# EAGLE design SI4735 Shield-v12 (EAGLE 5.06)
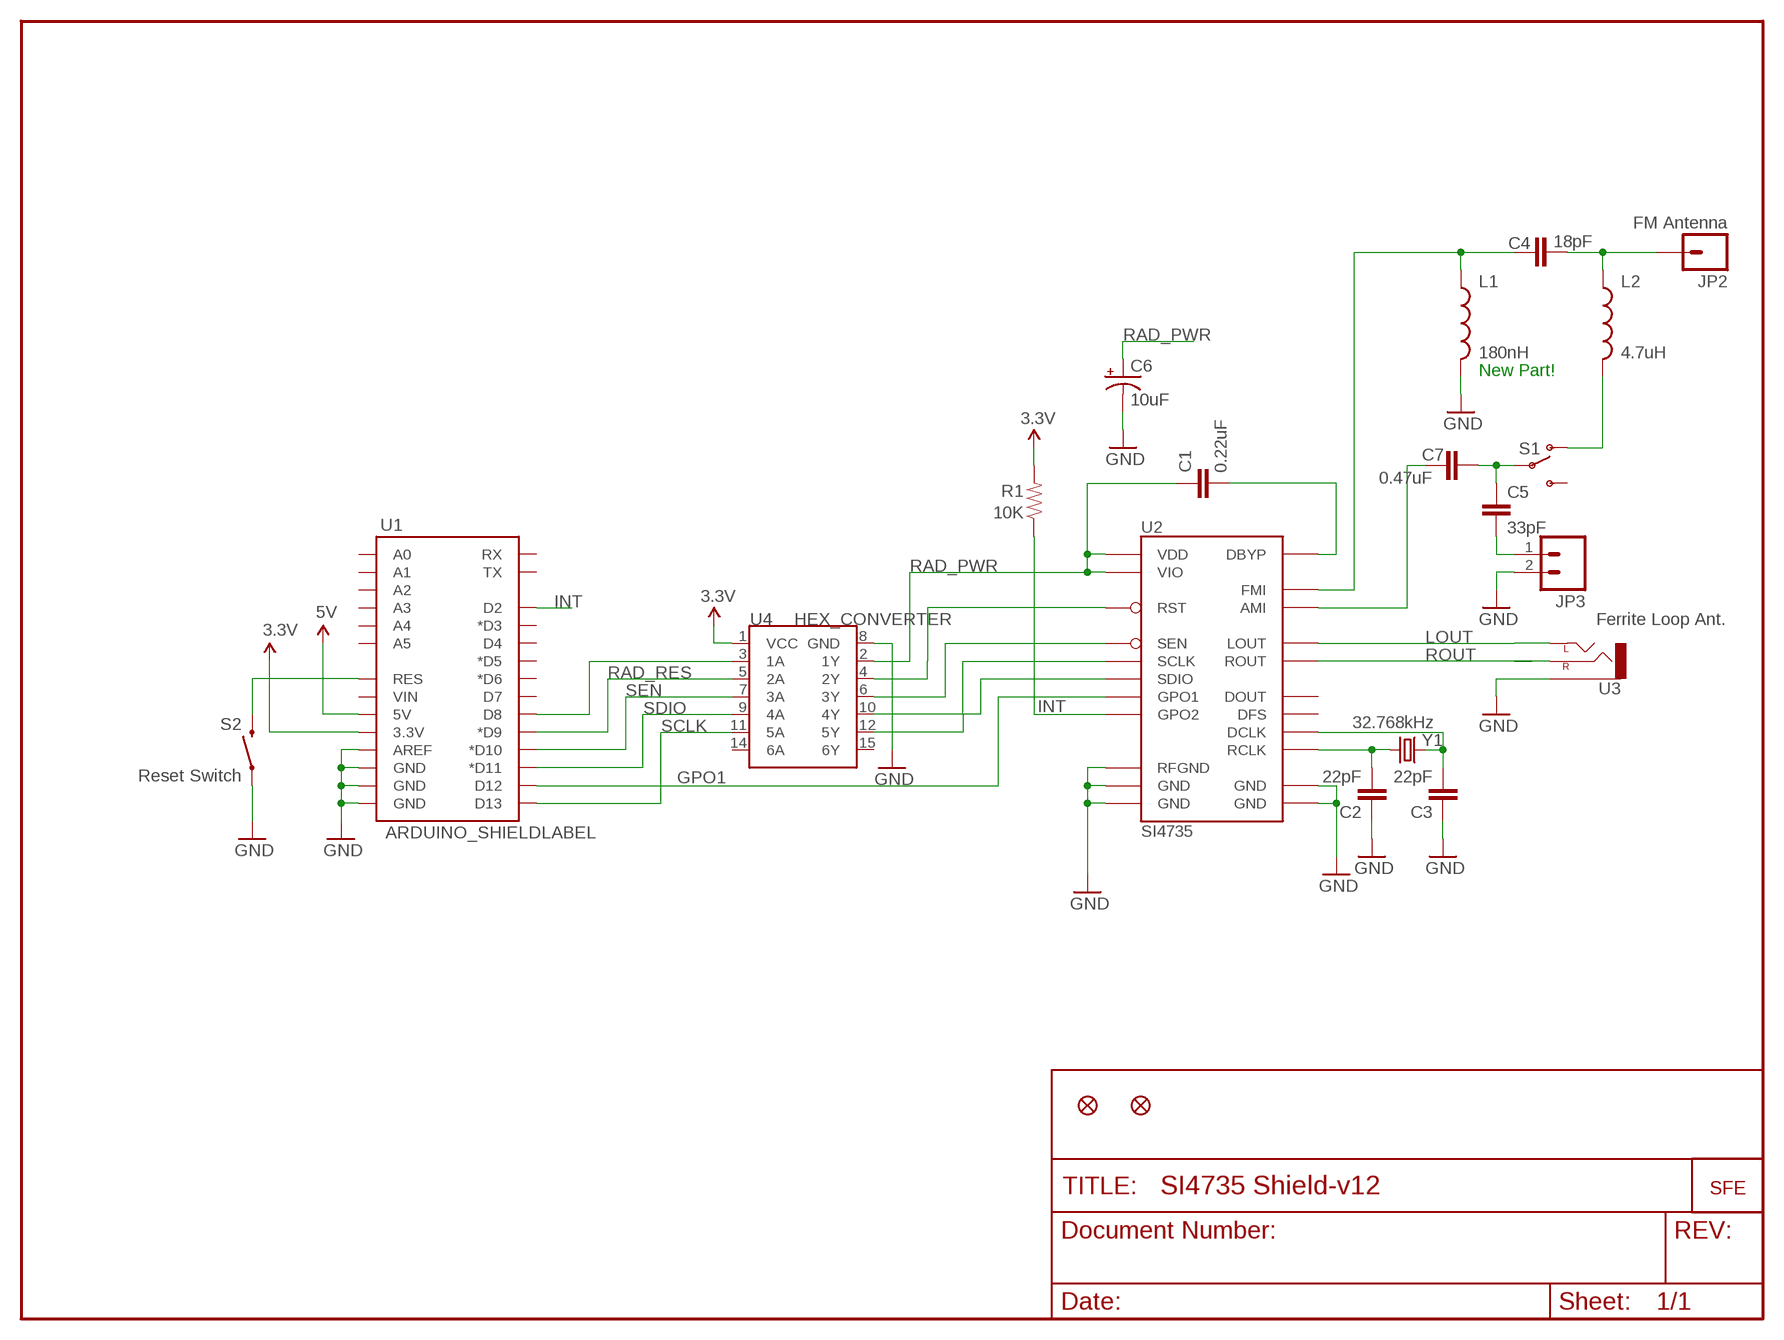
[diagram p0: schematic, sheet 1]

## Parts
C1  0.22uF  CAP0402-CAP  [0402-CAP]
C2  22pF  CAP0402-CAP  [0402-CAP]
C3  22pF  CAP0402-CAP  [0402-CAP]
C4  18pF  CAP0402-CAP  [0402-CAP]
C5  33pF  CAP0402-CAP  [0402-CAP]
C6  10uF  CAP_POL3528  [EIA3528]
C7  0.47uF  CAP0402-CAP  [0402-CAP]
JP1  LOGO-SFENEW  [SFE-NEW-WEBLOGO]
JP2  FM Antenna  M01PTH  [1X01]
JP3  Ferrite Loop Ant.  M02PTH  [1X02]
JP4  FIDUCIAL1X2  [FIDUCIAL-1X2]
JP5  FIDUCIAL1X2  [FIDUCIAL-1X2]
L1  180nH  INDUCTOR0402  [C0402]
L2  4.7uH  INDUCTOR0402  [C0402]
R1  10K  RESISTOR0402-RES  [0402-RES]
S1  SWITCH-SPSTSMD  [AYZ0202]
S2  Reset Switch  SWITCH-MOMENTARY-2SMD  [TACTILE_SWITCH_SMD]
U1  ARDUINO_SHIELDLABEL  [DUEMILANOVE_SHIELD]
U2  SI4735  [SSOP24_NARROW]
U3  AUDIO-JACKSMD2  [AUDIO-JACK-3.5MM-SMD]
U4  HEX_CONVERTER  [SO016]
Y1  32.768kHz  CRYSTAL32-SMD  [CRYSTAL-32KHZ-SMD]

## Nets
3.3V: R1.2 U1.3.3V U4.1(VCC)
5V: U1.5V
GND: C2.1 C3.1 C6.C(-) JP3.2 L1.2 S2.1 U1.AREF U1.GND@0(GND) U1.GND@1(GND) U1.GND@2(GND) U2.9(RFGND) U2.10(GND) U2.11(GND) U2.13(GND) U2.14(GND) U3.SLEEVE U4.8(GND)
GPO1: U1.D12 U2.5(GPO1)
INT: R1.1 U1.D2 U2.4(GPO2)
LOUT: U2.24(LOUT) U3.TIP(LEFT)
N$1: C2.2 U2.19(RCLK) Y1.X1
N$2: C3.2 U2.3(DCLK) Y1.X2
N$3: S2.3 U1.RES
N$4: C1.2 U2.22(DBYP)
N$5: U2.15(RST) U4.4(2Y)
N$12: U2.16(SEN) U4.6(3Y)
N$15: U2.17(SCLK) U4.12(5Y)
N$16: U2.18(SDIO) U4.10(4Y)
N$17: C4.1 L1.1 U2.8(FMI)
N$20: U1.D8 U4.3(1A)
N$21: C4.2 JP2.1 L2.1
N$22: L2.2 S1.1(O)
N$23: C5.1 C7.1 S1.2(P)
N$34: C7.2 U2.12(AMI)
N$35: C5.2 JP3.1
RAD_PWR: C1.1 C6.A(+) U2.20(VIO) U2.21(VDD) U4.2(1Y)
RAD_RES: U1.D9(*D9) U4.5(2A)
ROUT: U2.23(ROUT) U3.RING(RIGHT)
SCLK: U1.D13 U4.11(5A)
SDIO: U1.D11(*D11) U4.9(4A)
SEN: U1.D10(*D10) U4.7(3A)
Unconnected: S1.3(S) U1.A0 U1.A1 U1.A2 U1.A3 U1.A4 U1.A5 U1.D3(*D3) U1.D4 U1.D5(*D5) U1.D6(*D6) U1.D7 U1.RX U1.TX U1.VIN U2.1(DOUT) U2.2(DFS) U4.14(6A) U4.15(6Y)

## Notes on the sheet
- New Part!

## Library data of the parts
C1-C5 C7 = SparkFun:CAP: Capacitor
C6 = SparkFun:CAP_POL: Capacitor Polarized
JP1 = SparkFun:LOGO-SFE: Spark Fun Electronics PCB Logo
JP2 = SparkFun:M01: Header 1
JP3 = SparkFun:M02: Header 2
JP4 JP5 = SparkFun:FIDUCIAL: Fiducial Alignment Points
L1 L2 = SparkFun:INDUCTOR: Inductors
R1 = SparkFun:RESISTOR: Resistor
S1 = SparkFun:SWITCH-SPST: SPST Switch Simple slide switch. Spark Fun Electronics SKU : COM-00102
S2 = SparkFun:SWITCH-MOMENTARY-2
U1 = SparkFun:ARDUINO_SHIELD
U2 = SparkFun:SI4735: Radio chip that covers FM broadcast with RDS, plus a bunch of shortwave and logwave frequencies
U3 = SparkFun:AUDIO-JACK: 3.5mm Audio Jack Simple 3.5mm common PCB mount audio jack. SKU: PRT-08032
U4 = SparkFun:HEX_CONVERTER
Y1 = SparkFun:CRYSTAL: Crystals

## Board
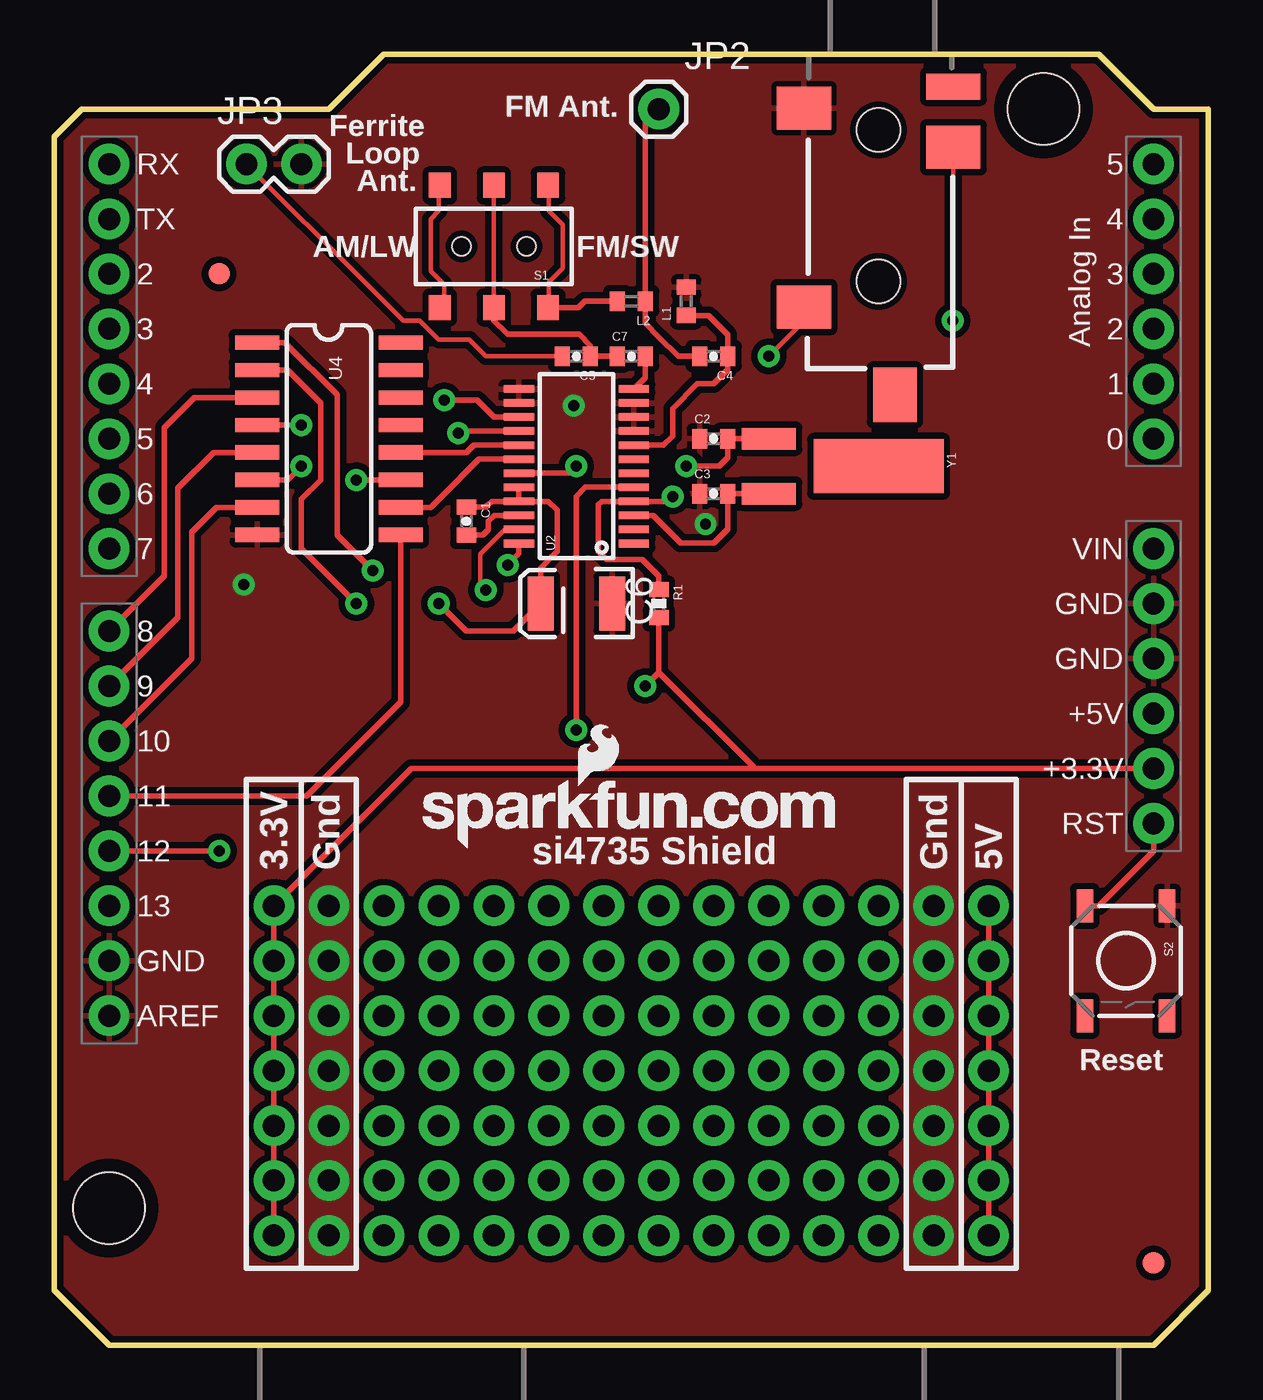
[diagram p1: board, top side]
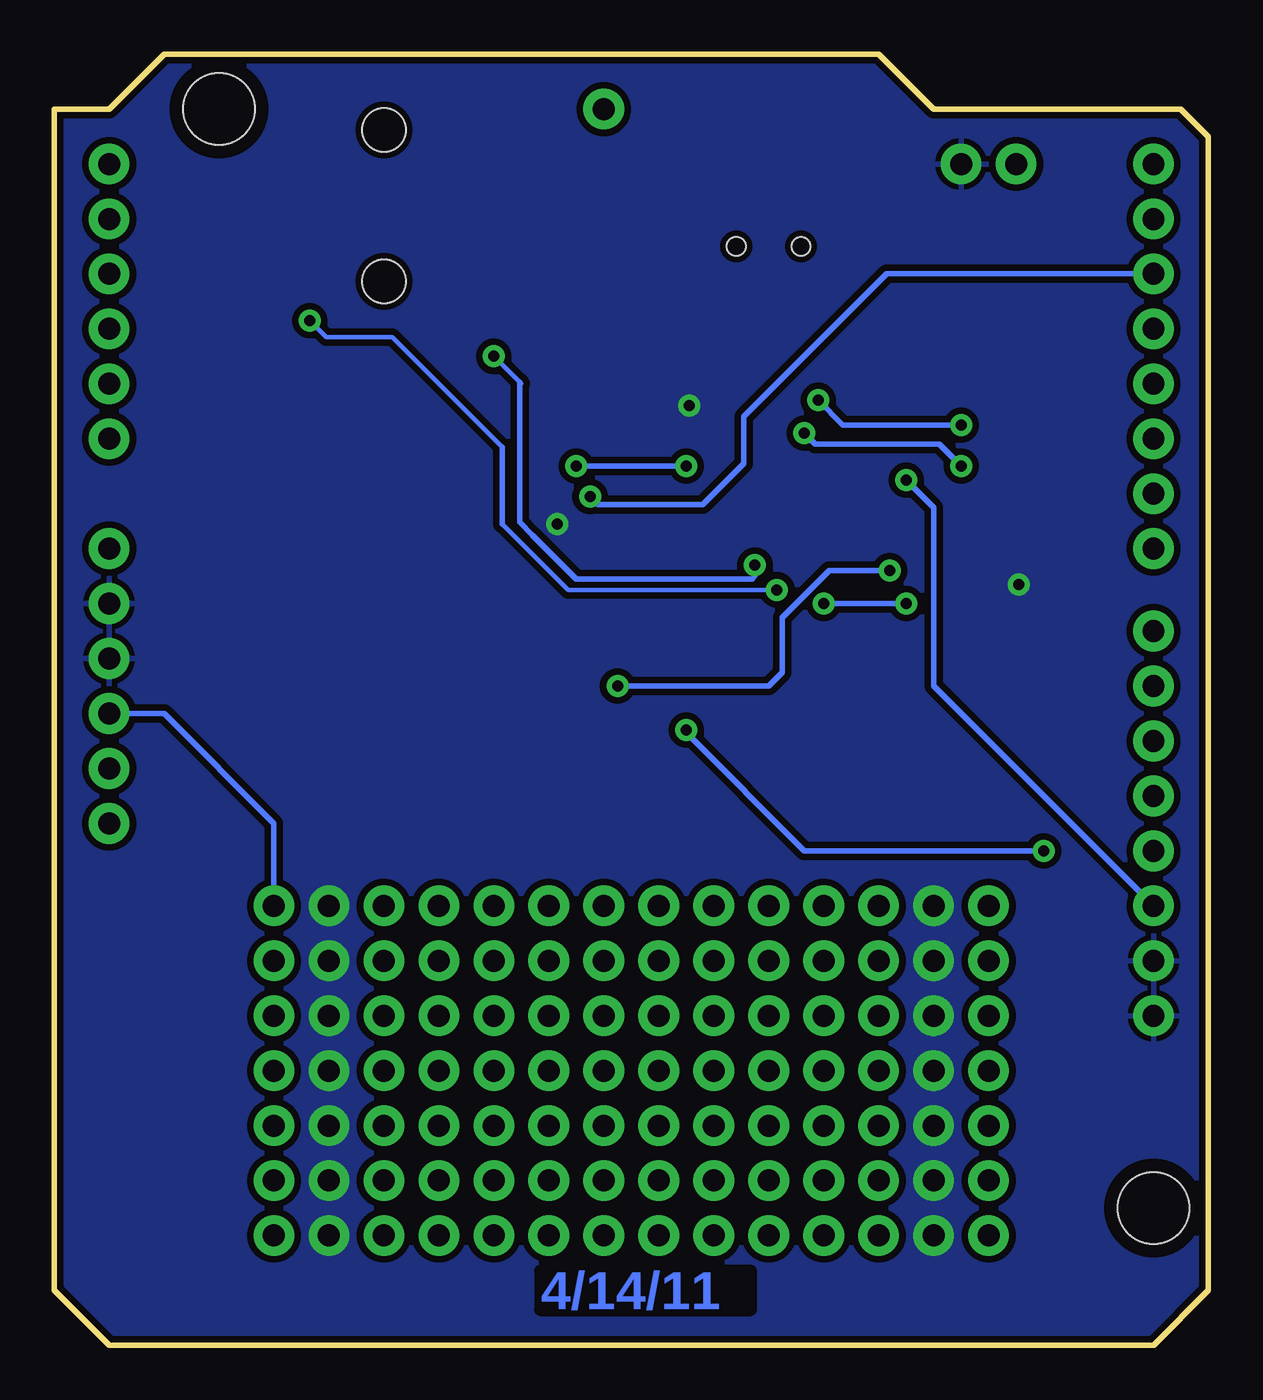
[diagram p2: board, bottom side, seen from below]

Size 53.34 x 59.69 mm. Coordinates in mm from the lower left corner, seen from the top.
Outline: 0,2.54 0,55.88 1.27,57.15 12.7,57.15 15.24,59.69 48.26,59.69 50.8,57.15 53.34,57.15 53.34,2.54 50.8,0 2.54,0 0,2.54
Copper layers (1*16): Top 0.035mm / dielectric 1.5mm / Bottom 0.035mm
Design rules "SparkFun": minimum track width 8mil, minimum drill 20mil, track to track 8mil, track to pad 8mil, pad to pad 8mil, via to via 8mil, smd to smd 8mil, copper to edge 8mil, drill to drill 8mil, minimum pad ring 12mil, minimum via ring 10mil, stop-mask expansion 4mil, vias tented up to drill 20mil, thermal gap 10mil

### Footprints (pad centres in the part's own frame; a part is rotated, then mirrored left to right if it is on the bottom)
0402-CAP = smd 0.7 x 0.9: 1 -0.65,0; 2 0.65,0
EIA3528 = smd 1.2 x 2.5: A 1.65,0; C -1.65,0
1X01 = drill 1.016 pad 1.88 round: 1 0,0
1X02 = drill 1.016 pad 1.88 round: 1 0,0; 2 2.54,0
FIDUCIAL-1X2 = smd 1 x 1: 1 0,0
C0402 = smd 0.7 x 0.9: 1 -0.65,0; 2 0.65,0
0402-RES = smd 0.7 x 0.9: 1 -0.65,0; 2 0.65,0
AYZ0202 = smd 1 x 1.15: 1 -2.5,2.825; 2 0,2.825; 3 2.5,2.825; 4 -2.5,-2.825; 5 0,-2.825; 6 2.5,-2.825 | hole 0.85: 1.5,0; -1.5,0
TACTILE_SWITCH_SMD = smd 1.524 x 0.762: 1 -2.54,1.905; 2 2.54,1.905; 3 -2.54,-1.905; 4 2.54,-1.905
DUEMILANOVE_SHIELD = drill 1.016 pad 1.88 round: 3.3V 50.8,26.67; 5V 50.8,29.21; A0 50.8,41.91; A1 50.8,44.45; A2 50.8,46.99; A3 50.8,49.53; A4 50.8,52.07; A5 50.8,54.61; AREF 2.54,15.24; D2 2.54,49.53; D3 2.54,46.99; D4 2.54,44.45; D5 2.54,41.91; D6 2.54,39.37; D7 2.54,36.83; D8 2.54,33.02; D9 2.54,30.48; D10 2.54,27.94; D11 2.54,25.4; D12 2.54,22.86; D13 2.54,20.32; GND@0 50.8,31.75; GND@1 50.8,34.29; GND@2 2.54,17.78; RES 50.8,24.13; RX 2.54,54.61; TX 2.54,52.07; VIN 50.8,36.83 | hole 3.302: 45.72,57.15; 2.54,6.35
SSOP24_NARROW = smd 0.348 x 1.397: 1 -3.575,-2.65; 2 -2.925,-2.65; 3 -2.275,-2.65; 4 -1.625,-2.65; 5 -0.975,-2.65; 6 -0.325,-2.65; 7 0.325,-2.65; 8 0.975,-2.65; 9 1.625,-2.65; 10 2.275,-2.65; 11 2.925,-2.65; 12 3.575,-2.65; 13 3.575,2.65; 14 2.925,2.65; 15 2.275,2.65; 16 1.625,2.65; 17 0.975,2.65; 18 0.325,2.65; 19 -0.325,2.65; 20 -0.975,2.65; 21 -1.625,2.65; 22 -2.275,2.65; 23 -2.925,2.65; 24 -3.575,2.65
AUDIO-JACK-3.5MM-SMD = smd 2 x 2.5: RING 4.3,3.45; SLEEVE 2.5,-3.45; TIP 11.7,-3.45 | smd 1.2 x 2.5: RSH 1.5,3.45 | smd 2.5 x 2: TSH 15.75,0.75 | hole 2: 3.5,0; 10.5,0
SO016 = smd 0.66 x 2.032: 1 -4.445,-3.315; 2 -3.175,-3.315; 3 -1.905,-3.315; 4 -0.635,-3.315; 5 0.635,-3.315; 6 1.905,-3.315; 7 3.175,-3.315; 8 4.445,-3.315; 9 4.445,3.315; 10 3.175,3.315; 11 1.905,3.315; 12 0.635,3.315; 13 -0.635,3.315; 14 -1.905,3.315; 15 -3.175,3.315; 16 -4.445,3.315
CRYSTAL-32KHZ-SMD = smd 2.5 x 6: SHEILD 0,5.08 | smd 1 x 2.5: X1 -1.27,0; X2 1.27,0

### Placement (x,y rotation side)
C1  19.05,38.1 270 top
C2  30.48,41.91 0 top
C3  30.48,39.37 0 top
C4  30.48,45.72 180 top
C5  24.13,45.72 180 top
C6  24.13,34.29 180 top
C7  26.67,45.72 0 top
JP1  17.02,22.99 0 top
JP2  27.94,57.15 0 top
JP3  8.89,54.61 0 top
JP4  50.8,3.81 0 top
JP5  7.62,49.53 0 top
L1  29.21,48.26 90 top
L2  26.67,48.26 180 top
R1  27.94,34.29 270 top
S1  20.32,50.8 180 top
S2  49.53,17.78 270 top
U1  0,0 0 top
U2  24.13,40.64 90 top
U3  38.1,59.69 270 top
U4  12.7,41.91 270 top
Y1  33.02,40.64 270 top

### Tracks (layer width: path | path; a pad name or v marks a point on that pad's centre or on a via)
3.3V  (via drill 0.51, 1.02 pad 1.88)
  Top 0.254: U4.1 10.67,46.35 13.08,43.94 13.08,39.88 13.08,37.47 v14.73,35.81 | 27.94,31.11 v27.3,30.48 | 27.94,31.11 R1.2 | U1.3.3V 32.38,26.67 32.32,26.73 | 32.32,26.73 27.94,31.11 | v10.16,5.08 v10.16,7.62 v10.16,10.16 v10.16,12.7 v10.16,15.24 v10.16,17.78 v10.16,20.32 16.51,26.67 32.26,26.67 32.32,26.73
  Bottom 0.254: v27.3,30.48 20.32,30.48 19.68,31.11 19.68,33.66 17.53,35.81 v14.73,35.81
5V  (via drill 1.02 pad 1.88)
  Top 0.254: v43.18,20.32 v43.18,17.78 v43.18,15.24 v43.18,12.7 v43.18,10.16 v43.18,7.62 v43.18,5.08
  Bottom 0.254: U1.5V 48.26,29.21 43.18,24.13 v43.18,20.32
GND  (via drill 0.51, 1.02 pad 1.88)
  other vias: 24,43.43 8.76,35.18 30.1,37.97 40.64,20.32 40.64,17.78 40.64,15.24 40.64,12.7 40.64,10.16 40.64,7.62 40.64,5.08 12.7,20.32 12.7,17.78 12.7,15.24 12.7,12.7 12.7,10.16 12.7,7.62 12.7,5.08
  pour Bottom (isolate 0.305): 0,0 0,59.69 53.34,59.69 53.34,0
  pour Top (isolate 0.305): 0,0 0,57.15 2.54,59.69 52.07,59.69 53.34,58.42 53.34,2.54 50.8,0
GPO1  (via drill 0.51)
  Top 0.254: U2.5 25.06,39.66 24.55,39.66 24.13,39.24 v24.13,28.45 | U1.D12 v7.62,22.86
  Bottom 0.254: v24.13,28.45 24.13,28.32 18.67,22.86 v7.62,22.86
INT  (via drill 0.51)
  Top 0.254: R1.1 27.94,35.43 27.94,35.56 27.18,36.32 25.53,36.32 25.15,36.7 25.15,38.86 25.3,39.02 U2.4 28.35,39.02 v28.57,39.24
  Bottom 0.254: U1.D2 14.86,49.53 21.46,42.93 21.46,40.77 23.37,38.86 28.19,38.86 v28.57,39.24
LOUT  (via drill 0.51)
  Top 0.203: U3.TIP 34.65,47.35 v33.02,45.72
  Top 0.254: U2.24 21.48,36.59 v20.95,36.07
  Bottom 0.203: 31.83,44.45 31.75,44.45 v33.02,45.72
  Bottom 0.254: v20.95,36.07 20.95,35.56 21.08,35.43 29.21,35.43 31.24,37.47 31.83,38.05 31.83,44.45 31.83,44.53
N$1  (via drill 0.51)
  Top 0.254: Y1.X1 32.89,41.91 C2.2 31.13,41.04 30.99,40.89 30.73,40.64 v29.21,40.64 | U2.19 23.8,40.31 v24.13,40.64
  Bottom 0.254: v24.13,40.64 v29.21,40.64
N$2
  Top 0.254: Y1.X2 C3.2 31.13,37.73 31.11,37.72 30.73,37.34 30.48,37.08 28.96,37.08 27.68,38.37 U2.3
N$3
  Top 0.254: U1.RES 50.8,22.86 48.26,20.32 48.13,20.32 S2.3
N$4
  Top 0.254: C1.2 19.8,37.45 20.07,37.72 20.07,38.1 20.33,38.37 U2.22
N$5  (via drill 0.51)
  Top 0.254: U4.4 v11.43,42.55 | U2.15 20.33,42.91 19.56,43.69 v18.03,43.69
  Bottom 0.254: v11.43,42.55 16.89,42.55 v18.03,43.69
N$6  (via drill 1.02 pad 1.88)
  other vias: 15.24,5.08
N$7  (via drill 1.02 pad 1.88)
  other vias: 17.78,5.08
N$8  (via drill 1.02 pad 1.88)
  other vias: 20.32,5.08
N$9  (via drill 1.02 pad 1.88)
  other vias: 22.86,5.08
N$10  (via drill 1.02 pad 1.88)
  other vias: 25.4,5.08
N$11  (via drill 1.02 pad 1.88)
  other vias: 27.94,5.08
N$12  (via drill 0.51)
  Top 0.254: U4.6 10.79,40.01 v11.43,40.64 | U2.16 18.77,42.27 v18.67,42.16
  Bottom 0.254: v18.67,42.16 18.16,41.66 14.99,41.66 12.45,41.66 v11.43,40.64
N$13  (via drill 1.02 pad 1.88)
  other vias: 30.48,5.08
N$14  (via drill 1.02 pad 1.88)
  other vias: 33.02,5.08
N$15
  Top 0.254: U4.12 19.05,41.27 19.3,41.53 19.39,41.62 U2.17
N$16
  Top 0.254: U4.10 17.4,38.73 17.91,39.24 19.63,40.97 U2.18
N$17
  Top 0.254: L1.1 30.24,47.61 31.11,46.74 31.13,46.72 C4.1 31.13,45.1 31.11,45.09 30.48,44.45 29.72,44.45 28.57,43.31 28.57,42.04 28.15,41.62 U2.8
N$18  (via drill 1.02 pad 1.88)
  other vias: 35.56,5.08
N$19  (via drill 1.02 pad 1.88)
  other vias: 38.1,5.08
N$20
  Top 0.254: U1.D8 5.08,35.56 5.08,42.42 6.48,43.81 U4.3
N$21
  Top 0.254: C4.2 29.72,45.72 28.83,45.72 27.94,46.61 27.3,47.24 27.3,48.26 L2.1 27.32,56.53 JP2.1
N$22
  Top 0.254: S1.1 24.23,47.98 24.51,48.26 24.64,48.26 L2.2
N$23
  Top 0.203: 20.32,47.88 20.32,53.59
  Top 0.254: C7.1 26.04,45.72 C5.1 24.78,46.21 24.26,46.74 24.13,46.74 20.95,46.74 20.32,47.37 20.32,47.88 S1.2
N$24  (via drill 1.02 pad 1.88)
  other vias: 38.1,7.62
N$25  (via drill 1.02 pad 1.88)
  other vias: 35.56,7.62
N$26  (via drill 1.02 pad 1.88)
  other vias: 33.02,7.62
N$27  (via drill 1.02 pad 1.88)
  other vias: 30.48,7.62
N$28  (via drill 1.02 pad 1.88)
  other vias: 27.94,7.62
N$29  (via drill 1.02 pad 1.88)
  other vias: 25.4,7.62
N$30  (via drill 1.02 pad 1.88)
  other vias: 22.86,7.62
N$31  (via drill 1.02 pad 1.88)
  other vias: 20.32,7.62
N$32  (via drill 1.02 pad 1.88)
  other vias: 17.78,7.62
N$33  (via drill 1.02 pad 1.88)
  other vias: 15.24,7.62
N$34
  Top 0.254: C7.2 27.3,45.72 27.3,44.74 U2.12
N$35
  Top 0.203: C5.2 19.94,45.72 19.18,46.48 19.05,46.48 17.78,46.48 16.89,47.37 16.64,47.37 16.13,47.37 14.35,49.15 JP3.1
N$36
  Top 0.203: 18.03,48.01 18.03,49.02 17.4,49.66 17.4,52.07 17.78,52.45 17.78,53.59
N$37
  Top 0.203: 22.86,48.01 22.86,49.15 23.5,49.78 23.5,51.82 22.86,52.45 22.86,53.72
N$38  (via drill 1.02 pad 1.88)
  other vias: 15.24,10.16
N$39  (via drill 1.02 pad 1.88)
  other vias: 17.78,10.16
N$40  (via drill 1.02 pad 1.88)
  other vias: 20.32,10.16
N$41  (via drill 1.02 pad 1.88)
  other vias: 22.86,10.16
N$42  (via drill 1.02 pad 1.88)
  other vias: 25.4,10.16
N$43  (via drill 1.02 pad 1.88)
  other vias: 27.94,10.16
N$44  (via drill 1.02 pad 1.88)
  other vias: 30.48,10.16
N$45  (via drill 1.02 pad 1.88)
  other vias: 33.02,10.16
N$46  (via drill 1.02 pad 1.88)
  other vias: 35.56,10.16
N$47  (via drill 1.02 pad 1.88)
  other vias: 38.1,10.16
N$52  (via drill 1.02 pad 1.88)
  other vias: 38.1,12.7
N$53  (via drill 1.02 pad 1.88)
  other vias: 35.56,12.7
N$54  (via drill 1.02 pad 1.88)
  other vias: 33.02,12.7
N$55  (via drill 1.02 pad 1.88)
  other vias: 30.48,12.7
N$56  (via drill 1.02 pad 1.88)
  other vias: 27.94,12.7
N$57  (via drill 1.02 pad 1.88)
  other vias: 25.4,12.7
N$58  (via drill 1.02 pad 1.88)
  other vias: 22.86,12.7
N$59  (via drill 1.02 pad 1.88)
  other vias: 20.32,12.7
N$60  (via drill 1.02 pad 1.88)
  other vias: 17.78,12.7
N$61  (via drill 1.02 pad 1.88)
  other vias: 15.24,12.7
N$66  (via drill 1.02 pad 1.88)
  other vias: 15.24,15.24
N$67  (via drill 1.02 pad 1.88)
  other vias: 17.78,15.24
N$68  (via drill 1.02 pad 1.88)
  other vias: 20.32,15.24
N$69  (via drill 1.02 pad 1.88)
  other vias: 22.86,15.24
N$70  (via drill 1.02 pad 1.88)
  other vias: 25.4,15.24
N$71  (via drill 1.02 pad 1.88)
  other vias: 27.94,15.24
N$72  (via drill 1.02 pad 1.88)
  other vias: 30.48,15.24
N$73  (via drill 1.02 pad 1.88)
  other vias: 33.02,15.24
N$74  (via drill 1.02 pad 1.88)
  other vias: 35.56,15.24
N$75  (via drill 1.02 pad 1.88)
  other vias: 38.1,15.24
N$80  (via drill 1.02 pad 1.88)
  other vias: 38.1,17.78
N$81  (via drill 1.02 pad 1.88)
  other vias: 35.56,17.78
N$82  (via drill 1.02 pad 1.88)
  other vias: 33.02,17.78
N$83  (via drill 1.02 pad 1.88)
  other vias: 30.48,17.78
N$84  (via drill 1.02 pad 1.88)
  other vias: 27.94,17.78
N$85  (via drill 1.02 pad 1.88)
  other vias: 25.4,17.78
N$86  (via drill 1.02 pad 1.88)
  other vias: 22.86,17.78
N$87  (via drill 1.02 pad 1.88)
  other vias: 20.32,17.78
N$88  (via drill 1.02 pad 1.88)
  other vias: 17.78,17.78
N$89  (via drill 1.02 pad 1.88)
  other vias: 15.24,17.78
N$94  (via drill 1.02 pad 1.88)
  other vias: 15.24,20.32
N$95  (via drill 1.02 pad 1.88)
  other vias: 20.32,20.32
N$96  (via drill 1.02 pad 1.88)
  other vias: 17.78,20.32
N$97  (via drill 1.02 pad 1.88)
  other vias: 22.86,20.32
N$98  (via drill 1.02 pad 1.88)
  other vias: 27.94,20.32
N$99  (via drill 1.02 pad 1.88)
  other vias: 25.4,20.32
N$100  (via drill 1.02 pad 1.88)
  other vias: 30.48,20.32
N$101  (via drill 1.02 pad 1.88)
  other vias: 33.02,20.32
N$102  (via drill 1.02 pad 1.88)
  other vias: 35.56,20.32
N$103  (via drill 1.02 pad 1.88)
  other vias: 38.1,20.32
RAD_PWR  (via drill 0.51)
  Top 0.254: C1.1 19.95,38.75 20.07,38.86 20.22,39.02 U2.21 | U2.20 21.48,39.64 21.46,39.62 21.48,39.61 U2.21 | U2.21 22.83,39.02 23.24,38.61 23.24,38.35 23.24,36.7 23.11,36.58 22.48,35.94 C6.A 21.21,33.02 20.45,33.02 20.32,33.02 19.05,33.02 v17.78,34.29 | U4.2 10.79,45.09 12.19,43.69 12.32,43.56 12.32,40.39 12.32,40.01 11.43,39.12 11.43,36.83 v13.97,34.29
  Bottom 0.254: v13.97,34.29 v17.78,34.29
RAD_RES
  Top 0.254: U1.D9 5.71,33.66 5.71,35.81 5.71,36.07 5.71,39.62 7.37,41.27 U4.5
ROUT  (via drill 0.51)
  Top 0.203: U2.23 20.82,37.72 20.32,37.21 20.07,36.96 19.68,36.58 19.68,35.81 19.68,35.18 v19.94,34.92 | U3.RING 41.55,47.39 v41.53,47.37
  Bottom 0.203: v19.94,34.92 29.59,34.92 32.51,37.85 32.64,37.97 | 32.64,41.53 36.83,45.72 37.72,46.61 38.23,46.61 40.77,46.61 v41.53,47.37
  Bottom 0.254: 32.64,37.97 32.64,41.53
SCLK  (via drill 0.51)
  Top 0.254: U4.11 15.88,40.01 v13.97,40.01
  Bottom 0.254: U1.D13 12.7,30.48 12.7,37.59 12.7,38.73 v13.97,40.01
SDIO
  Top 0.254: U1.D11 7.62,25.4 7.75,25.4 11.68,25.4 16.02,29.73 U4.9
SEN
  Top 0.254: U1.D10 6.35,31.75 6.35,34.54 6.35,34.67 6.35,37.59 7.49,38.73 U4.7

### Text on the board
Bottom: 4/14/11
tPlace: FM Ant. | Ferrite | Loop | Ant. | AM/LW | FM/SW | si4735 Shield | 3.3V | Gnd | Gnd | 5V | Reset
